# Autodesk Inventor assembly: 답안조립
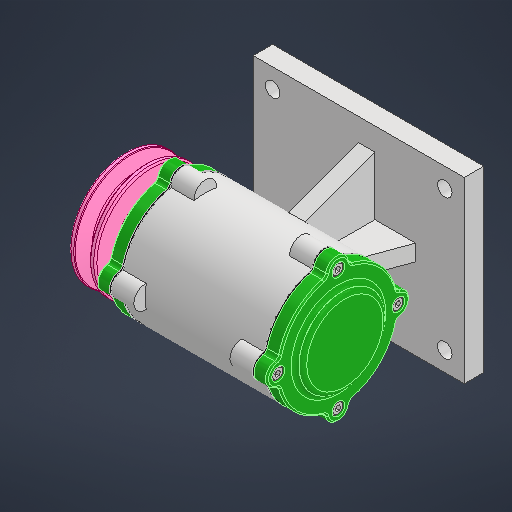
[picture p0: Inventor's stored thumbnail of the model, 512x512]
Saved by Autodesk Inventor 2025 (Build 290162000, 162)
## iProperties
Created: 2025-08
Part Number: 답안조립
Document SubType Name: Assembly
Designer: infra11
Author: infra11
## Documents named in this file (12)
- C:\Users\infra11\Desktop\750806V1010\답안조립.iam
- C:\Users\infra11\Desktop\750806V1010\본체.ipt
- C:\Users\infra11\Desktop\조세현\밀화부리\비둘기\V-벨트풀리\V-벨트풀리.ipt
- C:\Users\infra11\Desktop\조세현\밀화부리\비둘기\개스킷\개스킷.ipt
- C:\Users\infra11\Desktop\조세현\밀화부리\비둘기\너트 M12 x 1.25\너트 M12 x 1.25.ipt
- C:\Users\infra11\Desktop\조세현\밀화부리\비둘기\뒤커버\뒤커버.ipt
- C:\Users\infra11\Desktop\조세현\밀화부리\비둘기\베어링 6204\베어링 6204.ipt
- C:\Users\infra11\Desktop\조세현\밀화부리\비둘기\볼트 M4 x 12\볼트 M4 x 12.ipt
- C:\Users\infra11\Desktop\조세현\밀화부리\비둘기\앞커버\앞커버.ipt
- C:\Users\infra11\Desktop\조세현\밀화부리\비둘기\오일 실\오일 실.ipt
- C:\Users\infra11\Desktop\조세현\밀화부리\비둘기\축\축.ipt
- C:\Users\infra11\Desktop\조세현\밀화부리\비둘기\키 4 x 4\키 4 x 4.ipt
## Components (3 placed, 2 different names)
1. V-벨트풀리:1
2. 개스킷:1
3. 개스킷:2
